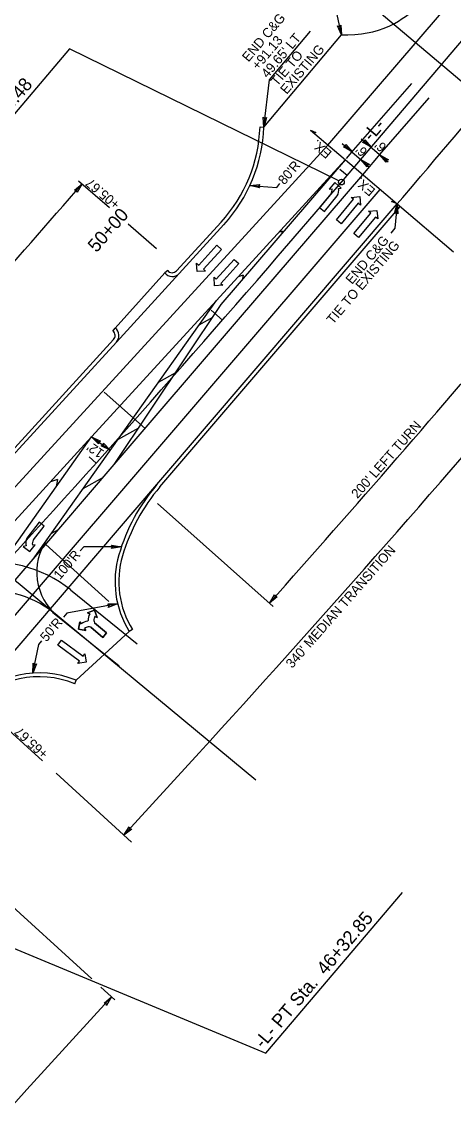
# Model space of a CAD drawing. Extents: x 1761082 to 1764358, y 421907 to 425434.
# Drawn here: x 1763787 to 1764013, y 424529 to 425108 of the extents above; entities that cross this region are included whole.
import ezdxf

# ---------------------------------------------------------------- set-up
doc = ezdxf.new("R2010")
doc.units = 0
for name, color, linetype in [('MARK HOOKS CENTER STRAIGHT LEFT TURN ARROW CELL', 7, 'Continuous'), ('MARK HOOKS STRAIGHT RIGHT TURN ARROW CELL', 7, 'Continuous'), ('MARK LEFT TURN ARROW CELL', 7, 'Continuous'), ('MARK STRAIGHT RIGHT ARROW CELL', 7, 'Continuous'), ('MARK UTURN ARROW CELL', 7, 'Continuous'), ('Prop Horizontal Alignment Tick Large', 7, 'Continuous'), ('Prop Mkg 3ft Min Skp 3ft Wide White', 7, 'Continuous'), ('Prop Mkg Min Skp 6ft Yellow', 7, 'Continuous'), ('Prop Mkg Skp Wht', 7, 'Continuous'), ('Prop Mkg Solid White Multiple Diagonals V8i', 7, 'Continuous'), ('Prop Mkg Solid Yel Skip LT', 7, 'Continuous'), ('Prop Mkg Solid Yel Skip RT', 7, 'Continuous'), ('Prop Mkg Solid Yellow Diagonals', 7, 'Continuous'), ('Prop Mkg Solid Yellow Edge Line', 7, 'Continuous'), ('Prop Mkg Solid Yellow Lane Line', 7, 'Continuous'), ('Prop Mkr CR 80ft Spc', 7, 'Continuous'), ('Scratch_Level_0', 7, 'Continuous'), ('Scratch_Level_5', 7, 'Continuous')]:
    doc.layers.add(name, color=color, linetype=linetype)

msp = doc.modelspace()

# ---------------------------------------------------------------- linework, layer by layer
at = {"layer": 'MARK HOOKS CENTER STRAIGHT LEFT TURN ARROW CELL'}
for p, q in [((1763957.43, 425027.13), (1763953.62, 425030.37)), ((1763826.06, 424876.34), (1763822.33, 424879.68))]:
    msp.add_line(p, q, dxfattribs=at)
at = {"layer": 'MARK LEFT TURN ARROW CELL'}
for p, q in [((1763911.87, 425052.61), (1763913.87, 425052.54)), ((1763859.44, 424863.82), (1763985.23, 425010.95)), ((1763985.23, 425010.95), (1763983.71, 425012.25)), ((1763868.12, 424977.17), (1763891.48, 425002.72)), ((1763863.54, 424977.35), (1763861.97, 424976.12)), ((1763834.85, 424945.52), (1763836.09, 424947.09)), ((1763769.8, 424869.63), (1763835.19, 424941.15)), ((1763845.07, 424788.99), (1763843.37, 424787.95)), ((1763814.82, 424760.57), (1763815.59, 424762.42))]:
    msp.add_line(p, q, dxfattribs=at)
for centre, radius, start, end in [((1763833.92, 425055.35), 78, 317.56143, 357.98457), ((1763865.91, 424979.19), 3, 217.9497, 317.56143), ((1763832.98, 424943.18), 3, 317.56143, 51.45869), ((1763933.92, 424800.13), 98, 139.47104, 163.6868), ((1763885.94, 424814.18), 48, 163.6868, 211.64232), ((1763796.27, 424716.3), 48, 67.26425, 137.61701)]:
    msp.add_arc(centre, radius, start, end, dxfattribs=at)
at = {"layer": 'MARK STRAIGHT RIGHT ARROW CELL'}
msp.add_line((1763954.51, 425023.69), (1764202.24, 425315.31), dxfattribs=at)
msp.add_arc((1758132.25, 429969.63), 7639.44, 317.617012, 319.652488, dxfattribs=at)
at = {"layer": 'MARK UTURN ARROW CELL'}
for points in [[(1763953.16, 425024.35), (1763812.18, 425093.6), (1763737.01, 425004.87)], [(1763647.64, 424678.18), (1763914.92, 424566.85), (1763986.41, 424651.23)]]:
    msp.add_lwpolyline(points, dxfattribs=at)
msp.add_circle((1763954.51, 425023.69), 1.5, dxfattribs=at)
at = {"layer": 'Prop Horizontal Alignment Tick Large'}
msp.add_line((1763892.24, 424951.31), (1763886.21, 424956.57), dxfattribs=at)
at = {"layer": 'Prop Mkg 3ft Min Skp 3ft Wide White'}
msp.add_line((1763954.51, 425023.69), (1764202.24, 425315.31), dxfattribs=at)
msp.add_arc((1758132.25, 429969.63), 7639.44, 317.617012, 319.652488, dxfattribs=at)
at = {"layer": 'Prop Mkg Skp Wht'}
for p, q in [((1763913.87, 425052.54), (1763954.47, 425100.88)), ((1763857.92, 424865.11), (1763983.71, 425012.25)), ((1763869.6, 424975.82), (1763892.96, 425001.37)), ((1763836.09, 424947.09), (1763861.97, 424976.12)), ((1763771.27, 424868.28), (1763836.67, 424939.8)), ((1763815.59, 424762.42), (1763843.37, 424787.95))]:
    msp.add_line(p, q, dxfattribs=at)
for points in [[(1763954.47, 425100.88), (1763957.84, 425100.88), (1763961.6, 425101.07), (1763964.96, 425101.43), (1763968.04, 425101.94), (1763970.97, 425102.56), (1763973.88, 425103.38), (1763976.91, 425104.46), (1763979.79, 425105.68), (1763982.26, 425106.9), (1763984.41, 425108.14), (1763986.36, 425109.4), (1763988.04, 425110.59), (1763989.4, 425111.63), (1763990.6, 425112.59), (1763991.8, 425113.56), (1763993.05, 425114.63), (1763994.38, 425115.91), (1763995.95, 425117.58), (1763997.9, 425119.8), (1763999.96, 425122.22)], [(1763983.71, 425012.25), (1763986.59, 425015.62), (1763991.65, 425021.56), (1763995.98, 425026.65), (1763999.85, 425031.2), (1764003.51, 425035.51), (1764006.98, 425039.58), (1764010.24, 425043.41), (1764013.57, 425047.33), (1764017.23, 425051.64), (1764021.23, 425056.34), (1764025.55, 425061.45), (1764030.17, 425066.9), (1764035.05, 425072.67), (1764040.19, 425078.74), (1764044.77, 425084.15)]]:
    msp.add_lwpolyline(points, dxfattribs=at)
for centre, radius, start, end in [((1763833.92, 425055.35), 80, 317.56143, 357.98457), ((1763865.91, 424979.19), 5, 217.9497, 317.56143), ((1763832.98, 424943.18), 5, 317.56143, 51.45869), ((1763933.92, 424800.13), 100, 139.47104, 163.6868), ((1763885.94, 424814.18), 50, 163.6868, 211.64232), ((1763796.27, 424716.3), 50, 67.26425, 137.61701)]:
    msp.add_arc(centre, radius, start, end, dxfattribs=at)
at = {"layer": 'Prop Mkg Solid White Multiple Diagonals V8i'}
for p, q in [((1763595.27, 425434.16), (1764358.27, 424787.77)), ((1763830.26, 424913.61), (1763851.74, 424894.56)), ((1763832.71, 424803.73), (1763799.62, 424833.72)), ((1763812.71, 424809.82), (1763847.59, 424781.64)), ((1763803.28, 424798.15), (1763838.16, 424769.97))]:
    msp.add_line(p, q, dxfattribs=at)
for centre, radius, start, end in [((1763824.96, 424819.2), 30, 144.67631, 231.05895), ((1763771.86, 424759.26), 65, 51.05895, 101.27803), ((1763771.86, 424759.26), 50, 51.05895, 101.27803)]:
    msp.add_arc(centre, radius, start, end, dxfattribs=at)
at = {"layer": 'Prop Mkg Solid Yel Skip RT'}
for p, q in [((1763954.87, 425043.91), (1763968.95, 425031.94)), ((1763964.87, 425046.33), (1763978.95, 425034.37)), ((1763957.17, 425036.09), (1763960.81, 425040.38)), ((1763965.67, 425027.57), (1763975.65, 425039.3)), ((1763816.88, 425024.38), (1763833.03, 425010.33)), ((1763983.71, 425012.25), (1764013.28, 424987.12)), ((1763842.91, 425001.73), (1763857.6, 424988.95)), ((1763823.69, 424890.05), (1763833.48, 424883.11)), ((1763918.82, 424801.08), (1763858.24, 424855.19)), ((1763766.37, 424748.95), (1763797.92, 424720.16)), ((1763840.59, 424681.22), (1763879.97, 424724.37)), ((1763805.03, 424713.67), (1763844.56, 424677.6)), ((1763751.92, 424671.43), (1763823.83, 424605.81)), ((1763828.46, 424601.58), (1763835.83, 424594.86)), ((1763789.78, 424547.78), (1763834.15, 424596.4))]:
    msp.add_line(p, q, dxfattribs=at)
for points in [[(1763954.47, 425100.88), (1763951.69, 425113.96), (1763967.61, 425132.75)], [(1763913.87, 425052.54), (1763916.79, 425077.35), (1763938.35, 425102.8)], [(1763906.55, 425021.82), (1763920.6, 425020.91), (1763922.26, 425022.87)], [(1763983.71, 425012.25), (1763982.45, 424999.47), (1763980.34, 424996.97)], [(1763839.28, 424832.42), (1763819.56, 424832.42), (1763817.77, 424830.3)], [(1763837.32, 424802.5), (1763810.71, 424797.69), (1763808.91, 424795.57)], [(1763792.82, 424766.18), (1763796.01, 424781.24), (1763797.67, 424783.2)]]:
    msp.add_lwpolyline(points, dxfattribs=at)
for centre, radius, start, end in [((1758076.76, 430009.28), 7605.02, 317.799981, 319.027687), ((1758176.09, 429920.01), 7690.24, 318.286985, 319.798859), ((1758132.25, 429969.63), 7781.32, 317.617012, 319.652488), ((1769289.17, 419529.14), 7445.13, 137.617012, 139.730103)]:
    msp.add_arc(centre, radius, start, end, dxfattribs=at)
at = {"layer": 'Prop Mkg Solid Yellow Diagonals'}
for p, q in [((1763951.02, 425023.41), (1763948.12, 425019.97)), ((1763948.12, 425019.97), (1763949.6, 425020.11)), ((1763954.38, 425020.56), (1763951.02, 425023.41)), ((1763952.9, 425020.42), (1763954.38, 425020.56)), ((1763948.89, 425017.45), (1763943.06, 425010.4)), ((1763945.6, 425008.3), (1763952.32, 425016.43)), ((1763951.89, 425003.89), (1763960.82, 425014.67)), ((1763959.67, 425015.63), (1763964.07, 425016.08)), ((1763960.82, 425014.67), (1763959.67, 425015.63)), ((1763964.07, 425016.08), (1763964.52, 425011.61)), ((1763943.06, 425010.4), (1763945.6, 425008.3)), ((1763963.36, 425012.57), (1763954.43, 425001.79)), ((1763964.52, 425011.61), (1763963.36, 425012.57)), ((1763968.72, 425008.41), (1763973.12, 425008.85)), ((1763969.88, 425007.45), (1763968.72, 425008.41)), ((1763973.12, 425008.85), (1763973.57, 425004.39)), ((1763954.43, 425001.79), (1763951.89, 425003.89)), ((1763960.94, 424996.67), (1763969.88, 425007.45)), ((1763972.42, 425005.34), (1763963.48, 424994.57)), ((1763973.57, 425004.39), (1763972.42, 425005.34)), ((1763963.48, 424994.57), (1763960.94, 424996.67)), ((1763879.78, 424980.19), (1763889.22, 424990.53)), ((1763889.22, 424990.53), (1763891.65, 424988.31)), ((1763891.65, 424988.31), (1763882.21, 424977.97)), ((1763878.91, 424976.72), (1763878.67, 424981.2)), ((1763878.67, 424981.2), (1763879.78, 424980.19)), ((1763888.93, 424972.81), (1763898.36, 424983.15)), ((1763900.8, 424980.92), (1763891.36, 424970.58)), ((1763898.36, 424983.15), (1763900.8, 424980.92)), ((1763883.32, 424976.96), (1763878.91, 424976.72)), ((1763882.21, 424977.97), (1763883.32, 424976.96)), ((1763888.06, 424969.33), (1763887.82, 424973.82)), ((1763887.82, 424973.82), (1763888.93, 424972.81)), ((1763892.47, 424969.57), (1763888.06, 424969.33)), ((1763891.36, 424970.58), (1763892.47, 424969.57)), ((1763796.13, 424845.31), (1763789.78, 424836.88)), ((1763793.26, 424836.02), (1763798.76, 424843.33)), ((1763798.76, 424843.33), (1763796.13, 424845.31)), ((1763789.38, 424832.86), (1763787.91, 424832.66)), ((1763787.91, 424832.66), (1763791.4, 424829.97)), ((1763791.4, 424829.97), (1763794.15, 424833.54)), ((1763794.15, 424833.54), (1763792.68, 424833.33)), ((1763821.45, 424797.75), (1763825.25, 424799.14)), ((1763825.25, 424799.14), (1763826.56, 424795.41)), ((1763822.67, 424797.23), (1763821.45, 424797.75)), ((1763821.9, 424793.74), (1763821.58, 424793.38)), ((1763826.56, 424795.41), (1763825.34, 424795.93)), ((1763816.83, 424789.21), (1763817.55, 424793.14)), ((1763820.7, 424788.49), (1763816.83, 424789.21)), ((1763817.55, 424793.14), (1763818.26, 424792.03)), ((1763819.98, 424789.61), (1763820.7, 424788.49)), ((1763829.57, 424784.93), (1763823.25, 424790.29)), ((1763825.24, 424792.57), (1763831.52, 424787.24)), ((1763806, 424780.78), (1763807.96, 424783.44)), ((1763807.96, 424783.44), (1763819.23, 424775.13)), ((1763831.52, 424787.24), (1763829.57, 424784.93)), ((1763817.27, 424772.47), (1763806, 424780.78)), ((1763819.23, 424775.13), (1763820.12, 424776.33)), ((1763820.12, 424776.33), (1763820.81, 424771.97)), ((1763816.38, 424771.26), (1763817.27, 424772.47)), ((1763820.81, 424771.97), (1763816.38, 424771.26))]:
    msp.add_line(p, q, dxfattribs=at)
for points in [[(1763825.35, 424795.94), (1763826.56, 424795.41), (1763825.25, 424799.14), (1763821.45, 424797.75), (1763822.67, 424797.23)], [(1763821.9, 424793.74), (1763821.58, 424793.38)], [(1763824.87, 424793.86), (1763824.87, 424793.86)], [(1763818.26, 424792.03), (1763817.55, 424793.14), (1763816.83, 424789.21), (1763820.7, 424788.49), (1763819.97, 424789.59)], [(1763821.96, 424790.43), (1763821.96, 424790.43)], [(1763823.24, 424790.29), (1763829.57, 424784.93), (1763831.52, 424787.24), (1763825.25, 424792.56)]]:
    msp.add_lwpolyline(points, dxfattribs=at)
for centre, radius, start, end in [((1763946.38, 425019.53), 3.27, 320.4145, 10.07267), ((1763947.83, 425019.11), 5.25, 329.09057, 14.40227), ((1763794.39, 424834.4), 5.25, 151.70718, 197.01887), ((1763795.86, 424834.05), 3.27, 143.03111, 192.68928), ((1763822.45, 424786.46), 6.97, 97.16687, 127.01965), ((1763822.45, 424786.46), 6.97, 97.16687, 127.01965), ((1763828.86, 424794.02), 6.97, 152.60308, 182.29849), ((1763828.86, 424794.02), 6.97, 152.60308, 182.29849), ((1763828.86, 424794.02), 4, 151.36319, 182.29333), ((1763828.86, 424794.02), 4, 151.36319, 182.29333), ((1763827.14, 424793.82), 2.28, 178.80325, 213.56927), ((1763827.14, 424793.82), 2.28, 178.80325, 213.56927), ((1763822.45, 424786.46), 4, 97.16687, 128.37955), ((1763822.45, 424786.46), 4, 97.16687, 128.37955), ((1763822.38, 424788.19), 2.28, 67.65901, 100.65696), ((1763822.38, 424788.19), 2.28, 67.65901, 100.65696)]:
    msp.add_arc(centre, radius, start, end, dxfattribs=at)
at = {"layer": 'Prop Mkg Solid Yellow Edge Line'}
for p, q in [((1763947.38, 425043.11), (1764006.91, 425112.48)), ((1763960.81, 425040.38), (1763991.32, 425075.48)), ((1763975.65, 425039.3), (1764000.45, 425067.94)), ((1763718.44, 424792.72), (1763947.38, 425043.11)), ((1763900.57, 424951.57), (1763965.67, 425027.57)), ((1763753.14, 424761.02), (1763974.82, 425019.8)), ((1763836.67, 424939.8), (1763869.6, 424975.82)), ((1763823.69, 424890.05), (1763889.08, 424961.57)), ((1763835.45, 424875.55), (1763900.57, 424951.57)), ((1763762.01, 424752.93), (1763857.92, 424865.11)), ((1763770.31, 424799.5), (1763793, 424825.99))]:
    msp.add_line(p, q, dxfattribs=at)
at = {"layer": 'Prop Mkg Solid Yellow Lane Line'}
for points in [[(1763954.27, 425106.05), (1763954.47, 425100.88), (1763952.52, 425105.71), (1763953.54, 425105.26)], [(1763915.34, 425057.5), (1763913.87, 425052.54), (1763913.57, 425057.74), (1763914.39, 425056.99)], [(1763956.74, 425043.47), (1763960.06, 425039.5), (1763955.56, 425042.13), (1763956.65, 425042.4)], [(1763966.7, 425045.93), (1763970.02, 425041.95), (1763965.52, 425044.58), (1763966.61, 425044.85)], [(1763977.92, 425034.1), (1763974.6, 425038.07), (1763979.09, 425035.44), (1763978.01, 425035.17)], [(1763967.96, 425031.64), (1763964.64, 425035.61), (1763969.13, 425032.98), (1763968.05, 425032.71)], [(1763814.74, 425019.43), (1763818.75, 425022.71), (1763816.07, 425018.24), (1763815.81, 425019.33)], [(1763911.59, 425020.61), (1763906.55, 425021.82), (1763911.73, 425022.4), (1763911.02, 425021.53)], [(1763982.34, 425007.26), (1763983.71, 425012.25), (1763984.11, 425007.05), (1763983.27, 425007.79)], [(1763827.35, 424886.38), (1763823.69, 424890.05), (1763828.4, 424887.82), (1763827.35, 424887.46)], [(1763829.83, 424886.78), (1763833.48, 424883.11), (1763828.77, 424885.34), (1763829.83, 424885.7)], [(1763834.18, 424833.3), (1763839.28, 424832.42), (1763834.15, 424831.51), (1763834.8, 424832.42)], [(1763920.81, 424806.16), (1763916.76, 424802.92), (1763919.49, 424807.36), (1763919.74, 424806.27)], [(1763832.14, 424802.46), (1763837.32, 424802.5), (1763832.43, 424800.69), (1763832.91, 424801.7)], [(1763794.74, 424770.99), (1763792.82, 424766.18), (1763793, 424771.39), (1763793.75, 424770.57)], [(1763844.68, 424684.39), (1763840.59, 424681.22), (1763843.39, 424685.62), (1763843.61, 424684.52)], [(1763830.18, 424593.07), (1763834.15, 424596.4), (1763831.52, 424591.89), (1763831.25, 424592.98)]]:
    msp.add_lwpolyline(points, close=True, dxfattribs=at)
at = {"layer": 'Prop Mkr CR 80ft Spc'}
msp.add_line((1763776.07, 424821.01), (1763909.73, 424710.27), dxfattribs=at)
at = {"layer": 'Scratch_Level_0'}
for p, q in [((1763889.08, 424961.57), (1763956.53, 425035.34)), ((1763891.52, 424959.44), (1763956.56, 425035.37)), ((1763943.93, 425021.09), (1763943.32, 425020.89)), ((1763943.93, 425021.09), (1763943.82, 425020.5)), ((1763923.47, 424997.99), (1763921.91, 424997.47)), ((1763923.47, 424997.99), (1763923.17, 424996.4)), ((1763903.01, 424974.84), (1763900.44, 424974)), ((1763903.01, 424974.84), (1763902.53, 424972.3)), ((1763793, 424825.99), (1763889.08, 424961.57)), ((1763835.45, 424875.55), (1763891.52, 424959.44)), ((1763880.08, 424948.87), (1763887.08, 424952.8)), ((1763858.78, 424918.81), (1763867.72, 424923.83)), ((1763837.48, 424888.75), (1763848.36, 424894.86)), ((1763768.01, 424829.16), (1763823.69, 424890.05)), ((1763780.25, 424828.76), (1763823.69, 424890.05)), ((1763793, 424825.99), (1763835.45, 424875.55)), ((1763819.27, 424863.06), (1763829.85, 424869)), ((1763805.83, 424867.65), (1763802.09, 424866.42)), ((1763805.83, 424867.65), (1763805.11, 424863.83)), ((1763802.52, 424839.42), (1763806.35, 424841.57))]:
    msp.add_line(p, q, dxfattribs=at)
at = {"layer": 'Scratch_Level_5'}
for p, q in [((1763938.23, 425050.88), (1763961.1, 425031.45)), ((1763961.1, 425031.45), (1763983.71, 425012.25))]:
    msp.add_line(p, q, dxfattribs=at)
for points in [[(1763938.23, 425050.88), (1763941.17, 425049.7), (1763939.99, 425049.38)], [(1763983.71, 425012.25), (1763980.78, 425013.43), (1763981.95, 425013.75)]]:
    msp.add_lwpolyline(points, close=True, dxfattribs=at)

# ---------------------------------------------------------------- texts
at = {"layer": 'MARK HOOKS STRAIGHT RIGHT TURN ARROW CELL'}
for s, rotation, p in [('-L-', 49.7301, (1763970.3, 425044.57)), ('50+00', 48.93642, (1763826.24, 424986.38))]:
    msp.add_text(s, height=7, rotation=rotation, dxfattribs=at).set_placement(p)
at = {"layer": 'MARK UTURN ARROW CELL'}
for s, p in [('-L- PT Sta.  50+95.48', (1763735.14, 425006.21)), ('-L- PT Sta.  46+32.85', (1763913.52, 424568.94))]:
    msp.add_text(s, height=7, rotation=49.7301, dxfattribs=at).set_placement(p)
at = {"layer": 'Prop Mkg Min Skp 6ft Yellow'}
for rotation, p in [(139.45026, (1763949.9, 425039.37)), (139.65249, (1763972.66, 425019.66))]:
    msp.add_text('EX.', height=5, rotation=rotation, dxfattribs=at).set_placement(p)
at = {"layer": 'Prop Mkg Solid Yel Skip LT'}
for s, rotation, p in [('END C&G', 49.7301, (1763905.82, 425086.36)), ('+91.13', 49.7301, (1763910.83, 425082.12)), ("49.65' LT", 49.7301, (1763915.83, 425077.89)), ('EXISTING', 49.7301, (1763925.83, 425069.41)), ('TIE TO ', 49.7301, (1763920.83, 425073.65)), ("6'", 137.61701, (1763978.5, 425042.65)), ("6'", 137.61701, (1763968.5, 425040.22)), ("80'R", 49.7301, (1763924.62, 425021.92)), ('+05.67', 139.7301, (1763838.97, 425012.77)), ('TIE TO EXISTING', 49.7301, (1763950.1, 424948.73)), ('END C&G', 49.7301, (1763960.04, 424969.74)), ("200' LEFT TURN", 48.6656, (1763962.93, 424857.42)), ("12'", 144.67631, (1763830.59, 424882.58)), ("100'R", 49.7301, (1763807.11, 424814.87)), ("340' MEDIAN TRANSITION", 48.6656, (1763928.65, 424768.39)), ("50'R", 49.7301, (1763800.03, 424782.25)), ('+65.67', 137.61701, (1763801.38, 424724.49))]:
    msp.add_text(s, height=5, rotation=rotation, dxfattribs=at).set_placement(p)

doc.saveas('drawing.dxf')
